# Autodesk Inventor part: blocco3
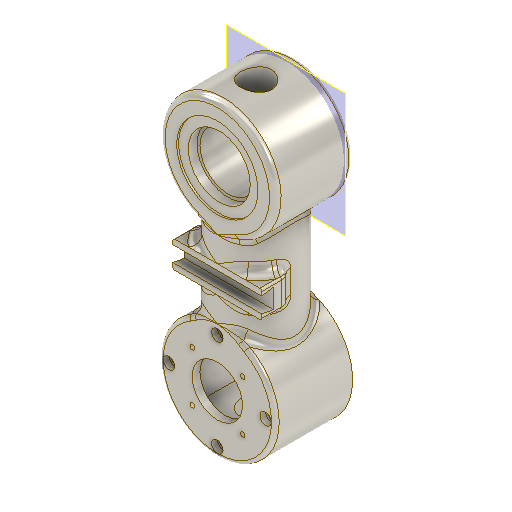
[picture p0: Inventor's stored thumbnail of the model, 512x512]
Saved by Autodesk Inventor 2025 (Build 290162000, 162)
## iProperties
Created: 2025-05
Part Number: blocco3
Material: Titanio
Document SubType Name: Modeling
Designer: 18907419
Density: 4.51 g/cm^3
Appearance: Titanio
alezza: 50,000 mm
Author: 18907419
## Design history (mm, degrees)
sketch "Schizzo1"
  geometry: C1 r 30 at (0, 0); 1 further point
  constraints: 1 centre point, 1 coincident
  dimensions: "d0" = 60 diameter of C1
extrude "Estrusione1" new body sketch "Schizzo1" stored distance "d1" = 40; taper "d2" = 0 deg
sketch "Schizzo2"
  geometry: L1 (-30, -20)-(30, -20) reference; L2 (30, 20)-(-30, 20) reference; L3 (30, -20)-(30, 20) reference; L4 (-30, -20)-(-30, 20) reference; C1 r 20 at (0, 0); 1 further point
  constraints: 1 centre point, 1 coincident
  dimensions: "d52" = 40 diameter of C1
extrude "Estrusione2" join sketch "Schizzo2" taper "d4" = 0 deg
sketch "Schizzo7"
  geometry: C1 r 8 at (0, 0); 1 further point
  constraints: 1 centre point, 1 coincident
  dimensions: "d19" = 16 diameter of C1
extrude "Estrusione7" cut sketch "Schizzo7" distance "d20" = 95.5; taper "d21" = 0 deg
sketch "Schizzo12"
  geometry: L1 (-17.55, 17.55)-(17.55, 17.55); L2 (17.55, 17.55)-(17.55, -17.55); L3 (17.55, -17.55)-(-17.55, -17.55); L4 (-17.55, -17.55)-(-17.55, 17.55); L5 (-17.55, 17.55)-(17.55, -17.55); L6 (17.55, 17.55)-(-17.55, -17.55); 1 further point
  constraints: 12 end point, 2 midpoint, 2 parallel, 1 horizontal, 1 perpendicular
  dimensions: "d38" = 35.1 distance of L2.end L3.end; "d39" = 35.1 distance of L1.end L2.end
extrude "Estrusione11" cut sketch "Schizzo12" distance "d40" = 60; taper "d41" = 0 deg
mirror "Speculare2"
sketch "Schizzo13"
  geometry: C1 r 16 at (0, 0); 1 further point
  constraints: 1 centre point
  dimensions: "d42" = 32 diameter of C1
extrude "Estrusione12" cut sketch "Schizzo13" extent not by distance; stored distance "d43" = 32; taper "d44" = 0 deg
mirror "Speculare3"
sketch "Schizzo18"
  geometry: L1 (-17.55, -17.55)-(-17.55, 17.55) reference; L2 (-17.55, 17.55)-(17.55, 17.55) reference; L3 (17.55, 17.55)-(17.55, -17.55) reference; L4 (17.55, -17.55)-(-17.55, -17.55) reference; C1 r 13 at (0, 0); C2 r 1.23 at (13.1, 13.1) reference; C3 r 1.23 at (13.1, -12.9) reference; C4 r 1.23 at (-12.9, -12.9) reference; C5 r 1.23 at (-12.9, 13.1) reference; 3 further points
  constraints: 1 centre point, 1 coincident, 1 vertical alignment
  dimensions: "d63" = 26 diameter of C1
  node "Linea chiusa proiettata5"
  node "Riferimento1"
  node "Riferimento2"
  node "Riferimento3"
  node "Riferimento4"
node "Piano di lavoro2"
extrude "Estrusione16" join sketch "Schizzo18" stored distance "d64" = 3; taper "d65" = 0 deg
sketch "Schizzo19"
  geometry: C1 r 1.7 at (0, 25) reference; 1 further point
hole "Foro3" sketch "Schizzo19" at (0, 25) diameter "d66" = 3.4; stored, may be unused: countersink angle "d70" = 90 deg, drill point angle "d72" = 118 deg; dims "d67" = 6, "d68" = 6.3, "d69" = 3.4, "d71" = 8
sketch "Schizzo20"
  geometry: C1 r 1.7 at (0, 25) reference; 2 further points
  constraints: 1 coincident
hole "Foro4" sketch "Schizzo20" at (0, 25) diameter "d76" = 3.4; stored, may be unused: countersink angle "d80" = 90 deg, drill point angle "d82" = 118 deg; dims "d77" = 6, "d78" = 6, "d79" = 3, "d81" = 8
pattern_circular "Serie circolare2" dims "d84" = 360 deg
fillet "Raccordo2" dims "d88" = 3
fillet "Raccordo3" dims "d89" = 5
fillet "Raccordo4" dims "d90" = 2
fillet "Raccordo5" dims "d91" = 2
node "Piano di lavoro3"
sketch "Schizzo23"
  geometry: L1 (0, 0)-(0, 100); L2 (20, 24.495)-(20, 75.505) reference; L3 (-23, 57)-(23, 57); L4 (23, 57)-(23, 43); L5 (23, 43)-(-23, 43); L6 (-23, 43)-(-23, 57); L7 (-23, 57)-(23, 43); L8 (23, 57)-(-23, 43); C1 r 10.7 at (0, 0) reference; C2 r 16 at (0, 100) reference; 2 further points
  constraints: 14 end point, 3 midpoint, 2 parallel, 1 coincident, 1 horizontal, 1 perpendicular, 1 vertical
  dimensions: "d104" = 46 distance of L4.end L5.end; "d105" = 14 distance of L3.end L4.end
extrude "Estrusione19" join sketch "Schizzo23" distance "d99" = 7; taper "d101" = 0 deg; dims "d100" = 6, "d102" = 0
fillet "Raccordo6" dims "d106" = 5
fillet "Raccordo7" dims "d107" = 5
sketch "Schizzo24"
  geometry: L1 (-10.38, 0)-(-10.38, 14) reference; L2 (-10.38, 0)-(0, 0) reference; L3 (0, 14)-(0, 0) reference; L4 (-10.38, 14)-(0, 14) reference; L5 (0, 7)-(-10.38, 7); L6 (0, 11)-(-6, 12.058); L7 (-6, 12.058)-(-6, 7); L8 (0, 3)-(-6, 1.942); L9 (-6, 1.942)-(-6, 7); L10 (0, 14)-(0, 0) reference; 3 further points
  constraints: 10 end point, 3 midpoint, 2 point on line, 2 symmetric about line, 1 perpendicular
  dimensions: "d108" = 6 distance between parallel lines of L7 L3; "d109" = 80 deg angle of L7 L6; "d113" = 4 distance of point (0, 7) L6.start
extrude "Estrusione20" cut sketch "Schizzo24" extent not by distance; stored distance "d110" = 0; taper "d111" = 0 deg
node "Piano di lavoro4"
sketch "Schizzo25"
  geometry: C1 r 14.5 at (0, 0); C2 r 16 at (0, 0) reference; 1 further point
  constraints: 1 centre point
  dimensions: "d115" = 29 diameter of C1
extrude "Estrusione21" join sketch "Schizzo25" distance "d116" = 30; taper "d117" = 0 deg
sketch "Schizzo26"
  geometry: C1 r 21 at (0, 0); 1 further point
  constraints: 1 centre point
  dimensions: "d118" = 42 diameter of C1
extrude "Estrusione22" cut sketch "Schizzo26" distance "d119" = 1; taper "d120" = 0 deg
fillet "Raccordo9" dims "d121" = 1
fillet "Raccordo10" dims "d122" = 5
node "Solido1"
node "Linea chiusa proiettata1"
node "Riferimento5"
node "Riferimento7"
node "Linea chiusa proiettata7"
other parameters: "d92" = 13, "d114" = -4.5
